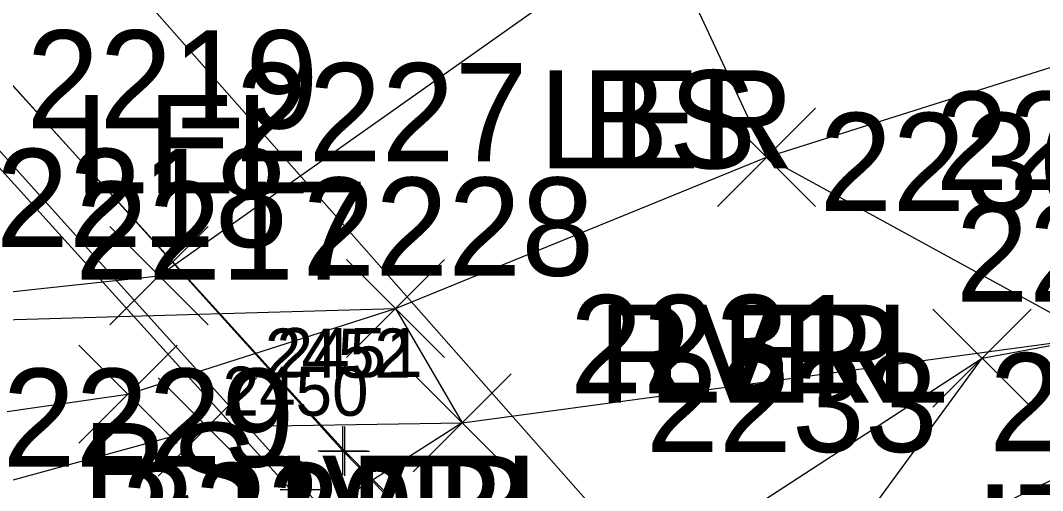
# Model space of a CAD drawing. Extents: x 1504228 to 1506103, y 437717 to 440106.
# Drawn here: x 1505265.52 to 1505286.34, y 438177.79 to 438187.37 of the extents above; entities that cross this region are included whole.
import ezdxf

# ---------------------------------------------------------------- set-up
doc = ezdxf.new("R2010")
doc.units = 0
for name, color, linetype in [('B_I', 7, 'Continuous'), ('B_TIC', 7, 'Continuous'), ('BB', 7, 'Continuous'), ('BF', 7, 'Continuous'), ('BR', 7, 'Continuous'), ('L_A', 7, 'Continuous'), ('L_I', 7, 'Continuous'), ('L_TIC', 7, 'Continuous'), ('LARO', 7, 'Continuous'), ('LAWE', 7, 'Continuous'), ('LELB', 7, 'Continuous'), ('UW', 7, 'Continuous')]:
    doc.layers.add(name, color=color, linetype=linetype)

msp = doc.modelspace()

# ---------------------------------------------------------------- linework, layer by layer
at = {"layer": 'B_TIC'}
for p, q in [((1505272.085, 438178.605), (1505272.161, 438178.605)), ((1505272.13, 438178.595), (1505272.205, 438178.595)), ((1505271.311, 438177.817), (1505271.386, 438177.817))]:
    msp.add_line(p, q, dxfattribs=at)
for points in [[(1505272.082, 438178.105), (1505272.082, 438179.105)], [(1505272.126, 438178.095), (1505272.126, 438179.095)], [(1505271.582, 438178.605), (1505272.582, 438178.605)], [(1505271.626, 438178.595), (1505272.626, 438178.595)], [(1505271.307, 438177.317), (1505271.307, 438178.317)], [(1505270.807, 438177.817), (1505271.807, 438177.817)]]:
    msp.add_lwpolyline(points, dxfattribs=at)
at = {"layer": 'BB'}
msp.add_lwpolyline([(1505279.36, 438168.588), (1505247.631, 438203.673)], dxfattribs=at)
at = {"layer": 'BF'}
for points in [[(1505211.925, 438243.921), (1505216.347, 438245.376), (1505218.618, 438242.78), (1505219.411, 438243.379), (1505231.883, 438226.243), (1505244.785, 438210.059), (1505258.149, 438194.034), (1505272.082, 438178.605), (1505279.641, 438170.867), (1505278.911, 438170.024), (1505281.091, 438167.856), (1505276.686, 438165.513)], [(1505219.325, 438243.288), (1505231.877, 438226.273), (1505244.695, 438209.964), (1505258.118, 438194.019), (1505272.126, 438178.595), (1505280.957, 438169.659)]]:
    msp.add_lwpolyline(points, dxfattribs=at)
at = {"layer": 'BR'}
msp.add_lwpolyline([(1505218.618, 438242.78), (1505231.125, 438225.649), (1505244.017, 438209.29), (1505257.36, 438193.318), (1505271.307, 438177.817), (1505278.911, 438170.024)], dxfattribs=at)
at = {"layer": 'L_TIC'}
for points in [[(1505279.716, 438183.584), (1505281.716, 438185.584)], [(1505281.716, 438183.584), (1505279.716, 438185.584)], [(1505279.716, 438183.584), (1505281.716, 438185.584)], [(1505281.716, 438183.584), (1505279.716, 438185.584)], [(1505267.339, 438181.172), (1505269.339, 438183.172)], [(1505269.339, 438181.172), (1505267.339, 438183.172)], [(1505272.159, 438180.503), (1505274.159, 438182.503)], [(1505274.159, 438180.503), (1505272.159, 438182.503)], [(1505272.159, 438180.503), (1505274.159, 438182.503)], [(1505274.159, 438180.503), (1505272.159, 438182.503)], [(1505284.106, 438179.489), (1505286.106, 438181.489)], [(1505286.106, 438179.489), (1505284.106, 438181.489)], [(1505284.106, 438179.489), (1505286.106, 438181.489)], [(1505286.106, 438179.489), (1505284.106, 438181.489)], [(1505266.708, 438178.756), (1505268.708, 438180.756)], [(1505268.708, 438178.756), (1505266.708, 438180.756)], [(1505273.516, 438178.171), (1505275.516, 438180.171)], [(1505275.516, 438178.171), (1505273.516, 438180.171)], [(1505273.516, 438178.171), (1505275.516, 438180.171)], [(1505275.516, 438178.171), (1505273.516, 438180.171)], [(1505268.325, 438178.089), (1505270.325, 438180.089)], [(1505270.325, 438178.089), (1505268.325, 438180.089)]]:
    msp.add_lwpolyline(points, dxfattribs=at)
at = {"layer": 'LARO'}
for points in [[(1505278.498, 438189.358), (1505280.716, 438184.584)], [(1505280.716, 438184.584), (1505287.419, 438180.921)], [(1505225.066, 438161.326), (1505226.248, 438169.057), (1505228.34, 438173.672), (1505225.288, 438173.876), (1505239.482, 438178.474), (1505243.528, 438176.585), (1505251.729, 438176.792), (1505258.116, 438181.066), (1505273.159, 438181.503), (1505274.516, 438179.171), (1505287.419, 438180.921)], [(1505211.067, 438140.867), (1505215.631, 438142.954), (1505229.653, 438148.999), (1505242.992, 438154.978), (1505245.889, 438156.33), (1505263.257, 438163.856), (1505270.634, 438167.43), (1505277.265, 438170.598), (1505281.289, 438172.305), (1505281.518, 438175.58), (1505285.106, 438180.489), (1505287.419, 438180.921)]]:
    msp.add_lwpolyline(points, dxfattribs=at)
at = {"layer": 'LAWE'}
msp.add_lwpolyline([(1505191.715, 438146.002), (1505202.906, 438148.803), (1505214.791, 438151.569), (1505218.42, 438155.881), (1505225.066, 438161.326), (1505233.297, 438167.151), (1505239.085, 438170.522), (1505246.461, 438173.024), (1505251.729, 438176.792), (1505260.319, 438178.7), (1505267.708, 438179.756), (1505273.159, 438181.503), (1505280.716, 438184.584), (1505293.606, 438188.67), (1505306.287, 438194.997), (1505316.183, 438195.439), (1505329.815, 438205.572), (1505347.823, 438213.433)], dxfattribs=at)
at = {"layer": 'LELB'}
for points in [[(1505258.116, 438181.066), (1505268.339, 438182.172), (1505278.498, 438189.358), (1505293.602, 438192.608), (1505306.445, 438196.96), (1505314.273, 438197.344), (1505329.9, 438207.293), (1505346.396, 438216.217), (1505367.728, 438232.021), (1505378.412, 438248.378), (1505391.234, 438272.553), (1505398.951, 438287.599)], [(1505215.631, 438142.954), (1505216.782, 438152.684), (1505223.21, 438155.651), (1505231.417, 438162.88), (1505240.87, 438166.496), (1505250.977, 438169.557), (1505260.591, 438172.084), (1505271.035, 438170.915), (1505277.265, 438170.598), (1505281.518, 438175.58), (1505287.828, 438178.641), (1505292.056, 438179.708), (1505296.753, 438181.832), (1505306.221, 438188.545)], [(1505233.297, 438167.151), (1505239.043, 438168.314), (1505249.04, 438172.836), (1505251.629, 438175.015), (1505261.788, 438177.035), (1505269.325, 438179.089), (1505274.516, 438179.171), (1505268.419, 438175.277), (1505270.919, 438173.353), (1505279.4, 438176.776), (1505285.106, 438180.489)]]:
    msp.add_lwpolyline(points, dxfattribs=at)
at = {"layer": 'UW'}
msp.add_lwpolyline([(1505283.181, 438170.638), (1505251.335, 438206.763), (1505225.076, 438243.18)], dxfattribs=at)

# ---------------------------------------------------------------- texts
at = {"layer": 'B_I'}
for s, p in [('2452', (1505270.497, 438180.095)), ('2451', (1505270.735, 438180.105)), ('2450', (1505269.634, 438179.317))]:
    msp.add_text(s, height=1, dxfattribs=at).set_placement(p)
at = {"layer": 'L_A'}
for s, p in [('LER', (1505276.081, 438184.358)), ('BS', (1505276.939, 438184.358)), ('LEL', (1505266.62, 438183.852)), ('RVRL', (1505277.283, 438179.584)), ('LER', (1505278.299, 438179.584)), ('BS', (1505266.78, 438177.172)), ('RVRL', (1505269.726, 438176.503)), ('LER', (1505270.741, 438176.503)), ('LER', (1505285.002, 438175.921)), ('LEL', (1505285.057, 438175.921)), ('TS', (1505285.829, 438175.921))]:
    msp.add_text(s, height=2, dxfattribs=at).set_placement(p)
at = {"layer": 'L_I'}
for s, p in [('2219', (1505265.638, 438185.172)), ('2227', (1505269.899, 438184.503)), ('2227', (1505269.899, 438184.503)), ('2237', (1505284.159, 438183.921)), ('2237', (1505284.159, 438183.921)), ('2237', (1505284.159, 438183.921)), ('2236', (1505281.791, 438183.489)), ('2236', (1505281.791, 438183.489)), ('2218', (1505265.016, 438182.756)), ('2217', (1505266.632, 438182.089)), ('2228', (1505271.256, 438182.171)), ('2228', (1505271.256, 438182.171)), ('2234', (1505284.568, 438181.641)), ('2231', (1505276.707, 438179.776)), ('2233', (1505278.258, 438178.58)), ('2233', (1505278.258, 438178.58)), ('2235', (1505285.251, 438178.592)), ('2229', (1505265.151, 438178.277)), ('2230', (1505267.573, 438176.353))]:
    msp.add_text(s, height=2, dxfattribs=at).set_placement(p)

doc.saveas('drawing.dxf')
